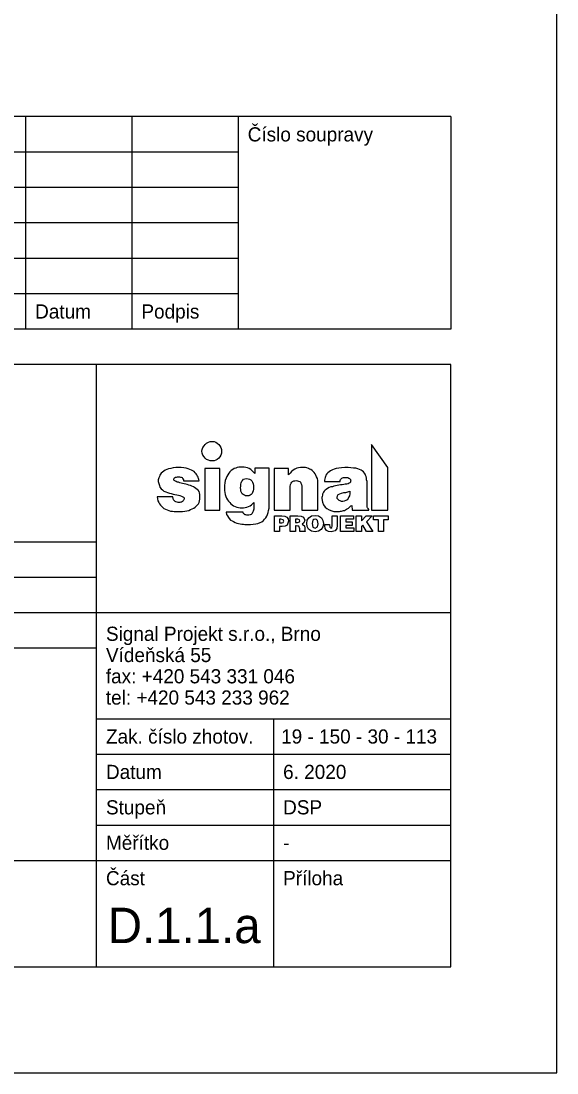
# Model space of a CAD drawing. Extents: x -790261 to -790051, y -987072 to -986775.
# Drawn here: x -790126.2 to -790050.6, y -987071.6 to -986923.1 of the extents above; entities that cross this region are included whole.
import ezdxf

# ---------------------------------------------------------------- set-up
doc = ezdxf.new("R2010")
doc.units = 0
for name, color, linetype in [('Info o rozpiskách', 7, 'Continuous'), ('popis', 7, 'Continuous'), ('Ramečky', 7, 'Continuous'), ('Rámečky-tisk', 7, 'Continuous'), ('Text', 7, 'Continuous'), ('Text barevný', 7, 'Continuous')]:
    doc.layers.add(name, color=color, linetype=linetype)

msp = doc.modelspace()

# ---------------------------------------------------------------- linework, layer by layer
at = {"layer": 'Info o rozpiskách'}
for points in [[(-790099.25, -986982.46), (-790098.98, -986982.47), (-790098.76, -986982.57), (-790098.54, -986982.7), (-790098.29, -986982.87), (-790098.15, -986983.07), (-790098.03, -986983.31), (-790097.94, -986983.58), (-790097.92, -986983.84), (-790097.94, -986984.1), (-790098.03, -986984.38), (-790098.15, -986984.62), (-790098.29, -986984.79), (-790098.54, -986984.99), (-790098.76, -986985.09), (-790098.98, -986985.18), (-790099.25, -986985.2), (-790099.54, -986985.18), (-790099.79, -986985.09), (-790100.05, -986984.99), (-790100.23, -986984.79), (-790100.4, -986984.62), (-790100.57, -986984.38), (-790100.65, -986984.1), (-790100.7, -986983.84), (-790100.65, -986983.58), (-790100.57, -986983.31), (-790100.4, -986983.07), (-790100.23, -986982.87), (-790100.05, -986982.7), (-790099.79, -986982.57), (-790099.54, -986982.47), (-790099.25, -986982.46)], [(-790090.48, -986992.94), (-790089.41, -986992.94), (-790089, -986992.98), (-790088.7, -986993.13), (-790088.52, -986993.37), (-790088.46, -986993.72), (-790088.65, -986994.25), (-790088.95, -986994.42), (-790089.38, -986994.47), (-790089.75, -986994.47), (-790089.75, -986995.16), (-790090.48, -986995.16), (-790090.48, -986992.94)], [(-790088.24, -986992.94), (-790087.16, -986992.94), (-790086.67, -986992.98), (-790086.35, -986993.13), (-790086.19, -986993.58), (-790086.3, -986993.93), (-790086.56, -986994.12), (-790086.24, -986994.34), (-790086.19, -986994.71), (-790086.19, -986994.88), (-790086.17, -986995.05), (-790086.11, -986995.11), (-790086.11, -986995.16), (-790086.86, -986995.16), (-790086.9, -986994.77), (-790087.03, -986994.42), (-790087.18, -986994.4), (-790087.4, -986994.38), (-790087.51, -986994.38), (-790087.51, -986995.16), (-790088.24, -986995.16), (-790088.24, -986992.94)], [(-790084.73, -986992.89), (-790084.23, -986992.96), (-790083.84, -986993.22), (-790083.63, -986993.59), (-790083.56, -986994.02), (-790083.63, -986994.49), (-790083.85, -986994.86), (-790084.23, -986995.12), (-790084.73, -986995.22), (-790085.25, -986995.12), (-790085.65, -986994.84), (-790085.83, -986994.47), (-790085.91, -986994.02), (-790085.83, -986993.58), (-790085.61, -986993.22), (-790085.23, -986992.96), (-790084.73, -986992.89)], [(-790082.33, -986992.94), (-790081.6, -986992.94), (-790081.6, -986994.32), (-790081.67, -986994.75), (-790081.88, -986995.05), (-790082.46, -986995.22), (-790082.83, -986995.18), (-790083.11, -986995.03), (-790083.29, -986994.75), (-790083.37, -986994.36), (-790083.35, -986994.19), (-790082.7, -986994.19), (-790082.66, -986994.56), (-790082.51, -986994.68), (-790082.38, -986994.6), (-790082.33, -986994.42), (-790082.33, -986992.94)], [(-790081.13, -986992.94), (-790079.32, -986992.94), (-790079.32, -986993.44), (-790080.4, -986993.44), (-790080.4, -986993.78), (-790079.49, -986993.78), (-790079.49, -986994.3), (-790080.4, -986994.3), (-790080.4, -986994.64), (-790079.27, -986994.64), (-790079.27, -986995.16), (-790081.13, -986995.16), (-790081.13, -986992.94)], [(-790078.91, -986992.94), (-790078.16, -986992.94), (-790078.16, -986993.65), (-790077.53, -986992.94), (-790076.67, -986992.94), (-790077.49, -986993.78), (-790076.58, -986995.16), (-790077.46, -986995.16), (-790078, -986994.28), (-790078.16, -986994.45), (-790078.16, -986995.16), (-790078.91, -986995.16), (-790078.91, -986992.94)], [(-790076.47, -986992.94), (-790074.41, -986992.94), (-790074.41, -986993.52), (-790075.07, -986993.52), (-790075.07, -986995.16), (-790075.8, -986995.16), (-790075.8, -986993.52), (-790076.47, -986993.52), (-790076.47, -986992.94)], [(-790089.75, -986993.44), (-790089.75, -986993.95), (-790089.43, -986993.95), (-790089.25, -986993.89), (-790089.15, -986993.69), (-790089.23, -986993.52), (-790089.54, -986993.44), (-790089.75, -986993.44)], [(-790087.51, -986993.44), (-790087.51, -986993.89), (-790087.19, -986993.89), (-790086.93, -986993.82), (-790086.88, -986993.69), (-790086.95, -986993.52), (-790087.16, -986993.44), (-790087.51, -986993.44)], [(-790084.73, -986993.43), (-790084.92, -986993.46), (-790085.05, -986993.58), (-790085.16, -986994.04), (-790085.05, -986994.53), (-790084.73, -986994.68), (-790084.38, -986994.49), (-790084.28, -986994.08), (-790084.4, -986993.61), (-790084.53, -986993.46), (-790084.73, -986993.43)]]:
    msp.add_lwpolyline(points, dxfattribs=at)
at = {"layer": 'popis'}
for points in [[(-790076.77, -986982.87), (-790076.77, -986992.14), (-790074.45, -986992.14), (-790074.45, -986986.11), (-790076.77, -986982.87)], [(-790103.29, -986988.02), (-790101.09, -986988.02), (-790101.15, -986987.83), (-790101.19, -986987.66), (-790101.24, -986987.49), (-790101.32, -986987.33), (-790101.41, -986987.18), (-790101.52, -986987.01), (-790101.63, -986986.86), (-790101.8, -986986.69), (-790101.97, -986986.6), (-790102.17, -986986.49), (-790102.4, -986986.39), (-790102.66, -986986.3), (-790102.94, -986986.24), (-790103.26, -986986.19), (-790103.61, -986986.15), (-790104, -986986.13), (-790104.4, -986986.15), (-790104.77, -986986.19), (-790105.09, -986986.26), (-790105.4, -986986.32), (-790105.66, -986986.41), (-790105.89, -986986.52), (-790106.07, -986986.65), (-790106.26, -986986.78), (-790106.43, -986986.93), (-790106.54, -986987.08), (-790106.65, -986987.23), (-790106.71, -986987.4), (-790106.78, -986987.59), (-790106.82, -986987.75), (-790106.86, -986987.89), (-790106.86, -986988.09), (-790106.8, -986988.39), (-790106.71, -986988.69), (-790106.62, -986988.91), (-790106.43, -986989.15), (-790106.26, -986989.28), (-790106.06, -986989.45), (-790105.81, -986989.56), (-790105.55, -986989.64), (-790105.29, -986989.73), (-790105.03, -986989.81), (-790104.77, -986989.88), (-790104.51, -986989.96), (-790104.25, -986989.99), (-790104.02, -986990.03), (-790103.8, -986990.09), (-790103.59, -986990.18), (-790103.39, -986990.25), (-790103.29, -986990.33), (-790103.22, -986990.42), (-790103.2, -986990.52), (-790103.24, -986990.68), (-790103.29, -986990.76), (-790103.33, -986990.85), (-790103.44, -986990.93), (-790103.57, -986991), (-790103.67, -986991.04), (-790103.8, -986991.08), (-790103.93, -986991.08), (-790104.06, -986991.08), (-790104.21, -986991.04), (-790104.38, -986990.98), (-790104.47, -986990.93), (-790104.6, -986990.8), (-790104.69, -986990.68), (-790104.77, -986990.5), (-790104.82, -986990.27), (-790107.01, -986990.27), (-790106.97, -986990.57), (-790106.9, -986990.83), (-790106.8, -986991.06), (-790106.69, -986991.24), (-790106.56, -986991.43), (-790106.41, -986991.6), (-790106.24, -986991.77), (-790106.06, -986991.9), (-790105.83, -986992.01), (-790105.61, -986992.12), (-790105.38, -986992.2), (-790105.14, -986992.27), (-790104.86, -986992.29), (-790104.62, -986992.34), (-790104.38, -986992.36), (-790104.06, -986992.36), (-790103.74, -986992.34), (-790103.43, -986992.34), (-790103.13, -986992.29), (-790102.83, -986992.23), (-790102.55, -986992.18), (-790102.31, -986992.08), (-790102.06, -986991.95), (-790101.86, -986991.86), (-790101.65, -986991.73), (-790101.47, -986991.56), (-790101.34, -986991.41), (-790101.2, -986991.24), (-790101.09, -986991.06), (-790101.02, -986990.83), (-790101, -986990.61), (-790101, -986990.39), (-790101, -986990.33), (-790101, -986990.27), (-790101, -986990.22), (-790101, -986990.16), (-790101, -986990.09), (-790101, -986990.03), (-790101, -986989.99), (-790101, -986989.96), (-790101.02, -986989.71), (-790101.11, -986989.53), (-790101.24, -986989.34), (-790101.39, -986989.21), (-790101.54, -986989.08), (-790101.73, -986988.93), (-790101.9, -986988.84), (-790102.12, -986988.76), (-790102.32, -986988.69), (-790102.55, -986988.61), (-790102.77, -986988.54), (-790102.98, -986988.5), (-790103.22, -986988.44), (-790103.43, -986988.39), (-790103.65, -986988.35), (-790103.84, -986988.3), (-790104.02, -986988.22), (-790104.19, -986988.18), (-790104.32, -986988.11), (-790104.45, -986988.07), (-790104.53, -986988.02), (-790104.64, -986987.94), (-790104.67, -986987.89), (-790104.67, -986987.81), (-790104.67, -986987.74), (-790104.64, -986987.66), (-790104.56, -986987.59), (-790104.49, -986987.55), (-790104.41, -986987.47), (-790104.28, -986987.47), (-790104.13, -986987.44), (-790104, -986987.44), (-790103.85, -986987.44), (-790103.72, -986987.47), (-790103.61, -986987.49), (-790103.5, -986987.55), (-790103.43, -986987.64), (-790103.39, -986987.74), (-790103.31, -986987.85), (-790103.29, -986988.02)], [(-790100.27, -986986.26), (-790100.27, -986992.14), (-790098.18, -986992.14), (-790098.18, -986986.26), (-790100.27, -986986.26)], [(-790093.24, -986986.24), (-790093.24, -986986.97), (-790093.41, -986986.77), (-790093.59, -986986.6), (-790093.8, -986986.43), (-790094.04, -986986.28), (-790094.28, -986986.17), (-790094.51, -986986.11), (-790094.75, -986986.08), (-790095.03, -986986.06), (-790095.29, -986986.08), (-790095.48, -986986.09), (-790095.74, -986986.13), (-790095.93, -986986.23), (-790096.15, -986986.28), (-790096.35, -986986.43), (-790096.58, -986986.54), (-790096.76, -986986.73), (-790096.91, -986986.92), (-790097.06, -986987.16), (-790097.19, -986987.4), (-790097.29, -986987.64), (-790097.4, -986987.96), (-790097.47, -986988.3), (-790097.51, -986988.67), (-790097.51, -986989.06), (-790097.51, -986989.38), (-790097.47, -986989.66), (-790097.4, -986989.92), (-790097.32, -986990.2), (-790097.23, -986990.44), (-790097.1, -986990.68), (-790096.93, -986990.89), (-790096.78, -986991.08), (-790096.62, -986991.24), (-790096.45, -986991.39), (-790096.22, -986991.52), (-790096, -986991.62), (-790095.78, -986991.71), (-790095.53, -986991.77), (-790095.29, -986991.8), (-790095.03, -986991.8), (-790094.81, -986991.8), (-790094.6, -986991.77), (-790094.34, -986991.73), (-790094.12, -986991.64), (-790093.91, -986991.54), (-790093.7, -986991.41), (-790093.56, -986991.28), (-790093.39, -986991.09), (-790093.39, -986991.64), (-790093.39, -986992.03), (-790093.46, -986992.29), (-790093.56, -986992.49), (-790093.63, -986992.64), (-790093.76, -986992.75), (-790093.91, -986992.79), (-790094.08, -986992.85), (-790094.26, -986992.85), (-790094.36, -986992.85), (-790094.49, -986992.83), (-790094.6, -986992.79), (-790094.69, -986992.75), (-790094.75, -986992.68), (-790094.84, -986992.61), (-790094.86, -986992.53), (-790094.9, -986992.44), (-790097.27, -986992.44), (-790097.21, -986992.74), (-790097.1, -986992.94), (-790096.97, -986993.17), (-790096.84, -986993.33), (-790096.67, -986993.54), (-790096.45, -986993.65), (-790096.24, -986993.74), (-790096, -986993.89), (-790095.78, -986993.97), (-790095.53, -986994.02), (-790095.31, -986994.08), (-790095.05, -986994.14), (-790094.84, -986994.15), (-790094.66, -986994.17), (-790094.43, -986994.19), (-790094.26, -986994.19), (-790093.85, -986994.17), (-790093.46, -986994.14), (-790093.09, -986994.08), (-790092.79, -986994.01), (-790092.49, -986993.91), (-790092.23, -986993.78), (-790092.03, -986993.63), (-790091.86, -986993.44), (-790091.69, -986993.24), (-790091.56, -986993.02), (-790091.45, -986992.77), (-790091.35, -986992.49), (-790091.32, -986992.2), (-790091.22, -986991.86), (-790091.22, -986991.51), (-790091.22, -986991.09), (-790091.22, -986986.24), (-790093.24, -986986.24)], [(-790090.5, -986986.26), (-790090.5, -986992.14), (-790088.26, -986992.14), (-790088.26, -986989.14), (-790088.26, -986988.82), (-790088.2, -986988.52), (-790088.11, -986988.35), (-790088.03, -986988.2), (-790087.9, -986988.11), (-790087.75, -986988.03), (-790087.57, -986988.02), (-790087.38, -986987.98), (-790087.19, -986988.02), (-790087.06, -986988.05), (-790086.9, -986988.11), (-790086.8, -986988.22), (-790086.73, -986988.35), (-790086.65, -986988.52), (-790086.62, -986988.78), (-790086.62, -986989.04), (-790086.62, -986992.14), (-790084.34, -986992.14), (-790084.34, -986988.59), (-790084.34, -986988.28), (-790084.36, -986987.98), (-790084.41, -986987.7), (-790084.51, -986987.44), (-790084.6, -986987.21), (-790084.71, -986987.01), (-790084.88, -986986.84), (-790084.99, -986986.67), (-790085.14, -986986.54), (-790085.31, -986986.41), (-790085.5, -986986.36), (-790085.68, -986986.26), (-790085.91, -986986.19), (-790086.09, -986986.15), (-790086.28, -986986.11), (-790086.5, -986986.11), (-790086.78, -986986.11), (-790087.06, -986986.19), (-790087.31, -986986.23), (-790087.57, -986986.36), (-790087.81, -986986.49), (-790088.05, -986986.67), (-790088.26, -986986.92), (-790088.5, -986987.18), (-790088.5, -986986.26), (-790090.5, -986986.26)], [(-790083.41, -986988.11), (-790081.19, -986988.11), (-790081.17, -986987.94), (-790081.13, -986987.81), (-790081.06, -986987.72), (-790080.96, -986987.64), (-790080.85, -986987.57), (-790080.7, -986987.53), (-790080.57, -986987.53), (-790080.42, -986987.53), (-790080.25, -986987.53), (-790080.09, -986987.55), (-790079.96, -986987.62), (-790079.88, -986987.66), (-790079.81, -986987.74), (-790079.73, -986987.81), (-790079.73, -986987.9), (-790079.69, -986988), (-790079.73, -986988.09), (-790079.75, -986988.2), (-790079.84, -986988.28), (-790079.94, -986988.35), (-790080.07, -986988.43), (-790080.25, -986988.46), (-790080.46, -986988.5), (-790080.66, -986988.54), (-790080.89, -986988.56), (-790081.13, -986988.59), (-790081.36, -986988.63), (-790081.6, -986988.67), (-790081.84, -986988.73), (-790082.08, -986988.76), (-790082.29, -986988.84), (-790082.51, -986988.87), (-790082.74, -986988.97), (-790082.96, -986989.08), (-790083.15, -986989.23), (-790083.31, -986989.32), (-790083.44, -986989.47), (-790083.54, -986989.62), (-790083.61, -986989.71), (-790083.67, -986989.88), (-790083.7, -986990.03), (-790083.74, -986990.2), (-790083.76, -986990.35), (-790083.76, -986990.52), (-790083.7, -986991), (-790083.56, -986991.39), (-790083.31, -986991.73), (-790083.05, -986991.93), (-790082.74, -986992.12), (-790082.38, -986992.25), (-790082.06, -986992.33), (-790081.73, -986992.34), (-790081.58, -986992.34), (-790081.45, -986992.33), (-790081.3, -986992.33), (-790081.13, -986992.29), (-790081.02, -986992.27), (-790080.85, -986992.25), (-790080.7, -986992.21), (-790080.57, -986992.18), (-790080.44, -986992.1), (-790080.31, -986992.03), (-790080.18, -986991.97), (-790080.03, -986991.88), (-790079.92, -986991.78), (-790079.81, -986991.67), (-790079.66, -986991.56), (-790079.55, -986991.47), (-790079.51, -986992.16), (-790077.12, -986992.16), (-790077.12, -986992.06), (-790077.25, -986991.93), (-790077.31, -986991.84), (-790077.36, -986991.75), (-790077.36, -986991.67), (-790077.4, -986991.56), (-790077.4, -986991.49), (-790077.4, -986991.37), (-790077.4, -986991.23), (-790077.4, -986988.35), (-790077.4, -986988.11), (-790077.46, -986987.87), (-790077.49, -986987.64), (-790077.53, -986987.42), (-790077.59, -986987.23), (-790077.64, -986987.08), (-790077.74, -986986.92), (-790077.9, -986986.75), (-790078.07, -986986.62), (-790078.24, -986986.51), (-790078.46, -986986.39), (-790078.71, -986986.3), (-790078.97, -986986.24), (-790079.3, -986986.21), (-790079.66, -986986.17), (-790080.07, -986986.11), (-790080.53, -986986.13), (-790081.02, -986986.17), (-790081.37, -986986.23), (-790081.73, -986986.28), (-790082.05, -986986.37), (-790082.29, -986986.47), (-790082.53, -986986.6), (-790082.74, -986986.73), (-790082.92, -986986.88), (-790083.05, -986987.03), (-790083.2, -986987.2), (-790083.28, -986987.38), (-790083.31, -986987.53), (-790083.37, -986987.72), (-790083.41, -986987.9), (-790083.41, -986988.11)], [(-790094.39, -986987.7), (-790094.19, -986987.74), (-790093.98, -986987.79), (-790093.8, -986987.89), (-790093.65, -986988.02), (-790093.56, -986988.2), (-790093.48, -986988.41), (-790093.41, -986988.67), (-790093.41, -986988.95), (-790093.41, -986989.19), (-790093.48, -986989.42), (-790093.54, -986989.64), (-790093.63, -986989.81), (-790093.74, -986989.92), (-790093.91, -986990.05), (-790094.08, -986990.11), (-790094.3, -986990.12), (-790094.53, -986990.11), (-790094.71, -986990.05), (-790094.9, -986989.92), (-790095.01, -986989.83), (-790095.1, -986989.64), (-790095.2, -986989.47), (-790095.23, -986989.25), (-790095.25, -986989.01), (-790095.23, -986988.74), (-790095.2, -986988.5), (-790095.16, -986988.28), (-790095.09, -986988.07), (-790094.99, -986987.94), (-790094.82, -986987.79), (-790094.64, -986987.74), (-790094.39, -986987.7)], [(-790079.81, -986989.47), (-790079.81, -986989.49), (-790079.81, -986989.55), (-790079.81, -986989.58), (-790079.84, -986989.84), (-790079.86, -986990.11), (-790079.96, -986990.29), (-790080.07, -986990.52), (-790080.22, -986990.68), (-790080.4, -986990.78), (-790080.61, -986990.87), (-790080.81, -986990.93), (-790080.98, -986990.93), (-790081.09, -986990.89), (-790081.21, -986990.83), (-790081.32, -986990.78), (-790081.43, -986990.7), (-790081.52, -986990.61), (-790081.6, -986990.52), (-790081.62, -986990.37), (-790081.58, -986990.12), (-790081.45, -986989.94), (-790081.22, -986989.83), (-790080.98, -986989.75), (-790080.66, -986989.68), (-790080.38, -986989.64), (-790080.09, -986989.55), (-790079.81, -986989.47)]]:
    msp.add_lwpolyline(points, dxfattribs=at)
at = {"layer": 'Ramečky'}
for p, q in [((-790065.59, -986936.6), (-790245.59, -986936.6)), ((-790125.59, -986936.6), (-790125.59, -986966.6)), ((-790110.59, -986936.6), (-790110.59, -986966.6)), ((-790095.59, -986936.6), (-790095.59, -986966.6)), ((-790065.59, -986936.6), (-790065.59, -986966.6)), ((-790095.59, -986941.6), (-790245.59, -986941.6)), ((-790095.59, -986946.6), (-790245.59, -986946.6)), ((-790095.59, -986951.6), (-790245.59, -986951.6)), ((-790095.59, -986956.6), (-790245.59, -986956.6)), ((-790095.59, -986961.6), (-790245.59, -986961.6)), ((-790065.59, -986966.6), (-790245.59, -986966.6)), ((-790065.59, -986971.6), (-790245.59, -986971.6)), ((-790115.59, -987056.6), (-790115.59, -986971.6)), ((-790065.59, -987056.6), (-790065.59, -986971.6)), ((-790245.59, -986996.6), (-790115.59, -986996.6)), ((-790245.59, -987001.6), (-790115.59, -987001.6)), ((-790245.59, -987006.6), (-790115.59, -987006.6)), ((-790245.59, -987011.6), (-790115.59, -987011.6)), ((-790115.59, -987021.6), (-790065.59, -987021.6)), ((-790115.59, -987026.6), (-790065.59, -987026.6)), ((-790115.59, -987031.6), (-790065.59, -987031.6)), ((-790115.59, -987036.6), (-790065.59, -987036.6)), ((-790245.59, -987041.6), (-790065.59, -987041.6)), ((-790245.59, -987056.6), (-790065.59, -987056.6))]:
    msp.add_line(p, q, dxfattribs=at)
for points in [[(-790115.59, -987006.6), (-790065.59, -987006.6)], [(-790090.59, -987021.6), (-790090.59, -987056.6)]]:
    msp.add_lwpolyline(points, dxfattribs=at)
at = {"layer": 'Rámečky-tisk'}
msp.add_lwpolyline([(-790260.59, -987071.6), (-790050.59, -987071.6), (-790050.59, -986774.6)], dxfattribs=at)

# ---------------------------------------------------------------- texts
at = {"layer": 'Text'}
for s, p in [('Číslo soupravy', (-790094.24, -986940.1)), ('Datum', (-790124.24, -986965.1)), ('Podpis', (-790109.24, -986965.1)), ('Signal Projekt s.r.o., Brno', (-790114.24, -987010.6)), ('Vídeňská 55', (-790114.24, -987013.6)), ('fax: +420 543 331 046', (-790114.26, -987016.6)), ('tel: +420 543 233 962', (-790114.26, -987019.6)), ('Zak. číslo zhotov.', (-790114.24, -987025.1)), ('19 - 150 - 30 - 113', (-790089.52, -987025.1)), ('Datum', (-790114.24, -987030.1)), ('6. 2020', (-790089.24, -987030.1)), ('Stupeň', (-790114.24, -987035.1)), ('DSP', (-790089.24, -987035.1)), ('Měřítko', (-790114.24, -987040.1)), ('-', (-790089.24, -987040.1)), ('Část', (-790114.24, -987045.1)), ('Příloha', (-790089.24, -987045.1))]:
    msp.add_text(s, height=2, dxfattribs=at).set_placement(p)
at = {"layer": 'Text barevný'}
msp.add_text('D.1.1.a', height=5, dxfattribs=at).set_placement((-790113.98, -987053.27))

doc.saveas('drawing.dxf')
